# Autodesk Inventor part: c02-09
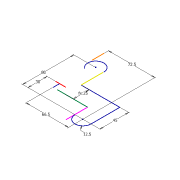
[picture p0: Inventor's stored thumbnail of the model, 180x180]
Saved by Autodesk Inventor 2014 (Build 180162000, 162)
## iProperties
Created: 2013-02
Part Number: c02-09
Material: Generic
Document SubType Name: Modeling
Designer: Thom Tremblay
Density: 1 g/cm^3
Appearance: Default
Author: Thom Tremblay
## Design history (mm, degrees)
sketch "Sketch1"
  geometry: L1 (-12.5, -13.8)-(-12.5, 20); L2 (-12.5, 20)-(-59.813, 20); L3 (-66.5, 20)-(-66.5, 30); L4 (-56.77, 30)-(-72.5, 30); L5 (-72.5, 87.066)-(-72.5, 105.75); L6 (-47.5, 78.673)-(-47.5, 45); L7 (-47.5, 45)-(12.5, 45); L8 (12.5, 45)-(12.5, 0); A1 r 12.5 centre (0, 0) between (-12.5, 0) and (12.5, 0); A2 r 12.5 centre (-60, 80) between (-47.5, 80) and (-67.398, 69.925); 1 further point
  constraints: 16 end point, 6 parallel, 4 point on circle, 4 tangent, 2 centre point, 2 point on line, 1 coincident, 1 equal radius, 1 perpendicular, 1 vertical
  dimensions: "d7" = 45 distance from line of A1.centre L7; "d8" = 12.5 radius of A1; "d9" = 25 distance between parallel lines of L7 L2 (= 2 x d8); "d11" = 66.5 distance from line of L3 A1.centre; "d12" = 30 distance from line of L4 A1.centre; "d13" = 80 vertical distance of A2.centre A1.centre; "d14" = 72.5 horizontal distance of A1.centre L5.end
